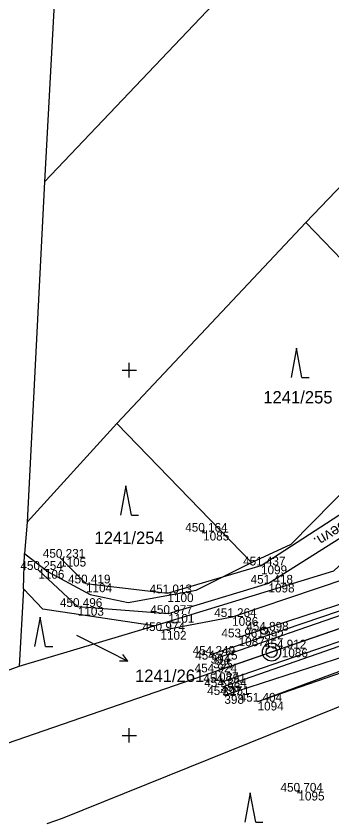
# Model space of a CAD drawing. Extents: x -776734 to -748832, y -1118122 to -976986.
# Drawn here: x -751615.5 to -751572.3, y -1114862.1 to -1114751.6 of the extents above; entities that cross this region are included whole.
import ezdxf

# ---------------------------------------------------------------- set-up
doc = ezdxf.new("R2010")
doc.units = 0
for name, color, linetype in [('KM_Hranice parcel', 7, 'Continuous'), ('KM_Parcelní čísla', 7, 'Continuous'), ('KM_Pop  PČ popisy', 7, 'Continuous'), ('KM_Značky kultur', 7, 'Continuous'), ('Level 61 Křížky', 7, 'Continuous'), ('OSA', 7, 'Continuous'), ('SŽG Vrstva 1', 7, 'Continuous'), ('SŽG Vrstva 4', 7, 'Continuous'), ('SŽG Vrstva 49', 7, 'Continuous'), ('SŽG Vrstva 51', 7, 'Continuous'), ('SŽG Vrstva 53', 7, 'Continuous'), ('SŽG Vrstva 60', 7, 'Continuous'), ('SŽG Vrstva 61', 7, 'Continuous'), ('SŽG Vrstva 7', 7, 'Continuous')]:
    doc.layers.add(name, color=color, linetype=linetype)

msp = doc.modelspace()

# ---------------------------------------------------------------- linework, layer by layer
at = {"layer": 'KM_Hranice parcel'}
for p, q in [((-751499.96, -1114656.64), (-751611.61, -1114774.25)), ((-751608.83, -1114722.39), (-751611.61, -1114774.25)), ((-751575.82, -1114779.78), (-751549.39, -1114752.11)), ((-751611.61, -1114774.25), (-751614, -1114820.83)), ((-751601.71, -1114807.3), (-751575.82, -1114779.78)), ((-751554.36, -1114802.22), (-751575.82, -1114779.78)), ((-751614, -1114820.83), (-751601.71, -1114807.3)), ((-751583.25, -1114826.36), (-751601.71, -1114807.3)), ((-751614, -1114820.83), (-751614.35, -1114825.11)), ((-751614.51, -1114829.93), (-751614.35, -1114825.11)), ((-751596.62, -1114835), (-751572.02, -1114827.5)), ((-751614.51, -1114829.93), (-751615.07, -1114840.52)), ((-751615.07, -1114840.52), (-751596.62, -1114835)), ((-751620.9, -1114842.7), (-751615.07, -1114840.52))]:
    msp.add_line(p, q, dxfattribs=at)
for points in [[(-751583.25, -1114826.36), (-751577.85, -1114823.81), (-751560.69, -1114806.38), (-751554.36, -1114802.22)], [(-751614.35, -1114825.11), (-751611.11, -1114827.63), (-751605.34, -1114830.73), (-751600.16, -1114831.83), (-751590.87, -1114830.15), (-751583.25, -1114826.36)], [(-751596.62, -1114835), (-751611.86, -1114832.73), (-751614.51, -1114829.93)], [(-751569.13, -1114845.24), (-751609.21, -1114861.38), (-751611.28, -1114862.12)]]:
    msp.add_lwpolyline(points, dxfattribs=at)
at = {"layer": 'KM_Pop  PČ popisy'}
for p, q in [((-751607.21, -1114836.31), (-751602.9, -1114838.49)), ((-751602.9, -1114838.49), (-751600.226, -1114839.852)), ((-751600.226, -1114839.852), (-751601.346, -1114839.844)), ((-751600.226, -1114839.852), (-751600.891, -1114838.952))]:
    msp.add_line(p, q, dxfattribs=at)
at = {"layer": 'KM_Značky kultur'}
for p, q in [((-751577.11, -1114797.02), (-751577.86, -1114801.02)), ((-751576.36, -1114801.02), (-751577.11, -1114797.02)), ((-751576.36, -1114801.02), (-751575.364, -1114801.02)), ((-751600.47, -1114815.84), (-751601.22, -1114819.84)), ((-751599.72, -1114819.84), (-751600.47, -1114815.84)), ((-751599.72, -1114819.84), (-751598.724, -1114819.84)), ((-751612.21, -1114833.84), (-751612.96, -1114837.84)), ((-751611.46, -1114837.84), (-751612.21, -1114833.84)), ((-751611.46, -1114837.84), (-751610.464, -1114837.84)), ((-751583.45, -1114857.87), (-751584.2, -1114861.87)), ((-751582.7, -1114861.87), (-751583.45, -1114857.87)), ((-751582.7, -1114861.87), (-751581.704, -1114861.87))]:
    msp.add_line(p, q, dxfattribs=at)
at = {"layer": 'Level 61 Křížky'}
for p, q in [((-751600, -1114800), (-751600, -1114799)), ((-751601, -1114800), (-751599, -1114800)), ((-751600, -1114801), (-751600, -1114800)), ((-751600, -1114850), (-751600, -1114849)), ((-751601, -1114850), (-751599, -1114850)), ((-751600, -1114851), (-751600, -1114850))]:
    msp.add_line(p, q, dxfattribs=at)
at = {"layer": 'OSA'}
msp.add_line((-751305.6868, -1114743.777), (-751648.6661, -1114862.1099), dxfattribs=at)
at = {"layer": 'SŽG Vrstva 1'}
msp.add_lwpolyline([(-751493.406, -1114808.538), (-751502.885, -1114811.809), (-751512.358, -1114815.079), (-751523.744, -1114819.014), (-751530.663, -1114821.401), (-751541.116, -1114825.002), (-751550.726, -1114828.317), (-751560.172, -1114831.578), (-751569.853, -1114834.918), (-751579.125, -1114838.113), (-751588.602, -1114841.381)], dxfattribs=at)
at = {"layer": 'SŽG Vrstva 4'}
for points in [[(-751531.222, -1114820.049), (-751532.411, -1114819.814), (-751547.631, -1114824.789), (-751568.7, -1114832.128), (-751588.868, -1114838.968)], [(-751531.222, -1114820.049), (-751547.578, -1114825.515), (-751568.497, -1114832.683), (-751588.528, -1114839.629)], [(-751529.854, -1114822.836), (-751546.799, -1114828.717), (-751567.35, -1114835.812), (-751587.5, -1114842.776)], [(-751529.854, -1114822.836), (-751530.62, -1114823.702), (-751546.636, -1114829.261), (-751567.254, -1114836.441), (-751587.282, -1114843.385)]]:
    msp.add_lwpolyline(points, dxfattribs=at)
at = {"layer": 'SŽG Vrstva 49'}
for p, q in [((-751589.669, -1114822.2351), (-751590.119, -1114822.0169)), ((-751589.7849, -1114821.901), (-751590.0031, -1114822.351)), ((-751534.993, -1114829.012), (-751582.438, -1114845.392)), ((-751576.621, -1114857.8241), (-751577.071, -1114857.6059)), ((-751576.7369, -1114857.49), (-751576.9551, -1114857.94))]:
    msp.add_line(p, q, dxfattribs=at)
for points in [[(-751564.092, -1114818.587), (-751543.018, -1114806.139), (-751536.934, -1114809.473), (-751533.922, -1114815.785), (-751539.386, -1114818.117), (-751585.925, -1114833.806), (-751595.742, -1114835.716)], [(-751535.601, -1114808.255), (-751531.347, -1114816.521), (-751539.042, -1114819.748), (-751551.843, -1114824.829), (-751553.747, -1114826.383), (-751585.03, -1114836.593)], [(-751586.983, -1114844.483), (-751566.691, -1114837.92), (-751546.322, -1114830.244), (-751529.778, -1114824.115), (-751528.71, -1114826.495)], [(-751535.416, -1114827.991), (-751582.438, -1114845.392)]]:
    msp.add_lwpolyline(points, dxfattribs=at)
at = {"layer": 'SŽG Vrstva 51'}
msp.add_lwpolyline([(-751609.483, -1114825.691), (-751605.933, -1114829.205), (-751594.773, -1114830.558), (-751581.97, -1114826.747), (-751566.399, -1114816.669), (-751540.967, -1114801.189), (-751532.595, -1114806.752), (-751528.368, -1114813.336), (-751525.848, -1114818.694), (-751529.358, -1114819.936), (-751530.249, -1114815.352), (-751535.601, -1114808.255), (-751541.69, -1114804.508), (-751564.092, -1114818.587), (-751580.945, -1114829.238), (-751594.664, -1114833.383), (-751607.051, -1114832.427), (-751612.458, -1114827.357)], dxfattribs=at)
at = {"layer": 'SŽG Vrstva 53'}
for points in [[(-751615.07, -1114840.52), (-751596.62, -1114835), (-751572.02, -1114827.5), (-751551.31, -1114808.23), (-751526.51, -1114811.39), (-751501.68, -1114801.88), (-751460.63, -1114785.23), (-751418.82, -1114768.72), (-751390.21, -1114757.9), (-751377.2, -1114753.63), (-751337.18, -1114740.99), (-751293.44, -1114727.24), (-751276.39, -1114722.19), (-751236.9, -1114707.02), (-751193.03, -1114664.28), (-751178.42, -1114675.26), (-751174.34, -1114678.03), (-751162.9, -1114674.22), (-751118.39, -1114659.47), (-751098.21, -1114652.66), (-751091.59, -1114651.24)], [(-751364.44, -1114782.53), (-751398.43, -1114791.82), (-751443.69, -1114804.18), (-751468.72, -1114811.03), (-751492.77, -1114816.96), (-751522.38, -1114824.27), (-751521.19, -1114833.04), (-751530.17, -1114829.56), (-751569.13, -1114845.24), (-751609.21, -1114861.38)]]:
    msp.add_lwpolyline(points, dxfattribs=at)
at = {"layer": 'SŽG Vrstva 60'}
for p, q in [((-751589.894, -1114822.126), (-751589.894, -1114822.126)), ((-751609.483, -1114825.691), (-751609.483, -1114825.691)), ((-751612.458, -1114827.357), (-751612.458, -1114827.357)), ((-751581.97, -1114826.747), (-751581.97, -1114826.747)), ((-751605.933, -1114829.205), (-751605.933, -1114829.205)), ((-751580.945, -1114829.238), (-751580.945, -1114829.238)), ((-751594.773, -1114830.558), (-751594.773, -1114830.558)), ((-751607.051, -1114832.427), (-751607.051, -1114832.427)), ((-751594.664, -1114833.383), (-751594.664, -1114833.383)), ((-751585.925, -1114833.806), (-751585.925, -1114833.806)), ((-751595.742, -1114835.716), (-751595.742, -1114835.716)), ((-751585.03, -1114836.593), (-751585.03, -1114836.593)), ((-751581.537, -1114835.673), (-751581.537, -1114835.673)), ((-751579.125, -1114838.113), (-751579.125, -1114838.113)), ((-751588.868, -1114838.968), (-751588.868, -1114838.968)), ((-751588.528, -1114839.629), (-751588.528, -1114839.629)), ((-751588.602, -1114841.381), (-751588.602, -1114841.381)), ((-751587.5, -1114842.776), (-751587.5, -1114842.776)), ((-751587.282, -1114843.385), (-751587.282, -1114843.385)), ((-751586.983, -1114844.483), (-751586.983, -1114844.483)), ((-751582.438, -1114845.392), (-751582.438, -1114845.392)), ((-751576.846, -1114857.715), (-751576.846, -1114857.715))]:
    msp.add_line(p, q, dxfattribs=at)
at = {"layer": 'SŽG Vrstva 7'}
msp.add_line((-751581.4897, -1114835.6567), (-751581.5843, -1114835.6893), dxfattribs=at)
for centre, radius in [((-751581.537, -1114835.673), 0.5), ((-751580.5287, -1114838.597), 1.2457), ((-751580.5287, -1114838.597), 0.7519)]:
    msp.add_circle(centre, radius, dxfattribs=at)

# ---------------------------------------------------------------- texts
at = {"layer": 'KM_Parcelní čísla'}
for s, p in [('1241/255', (-751581.66, -1114804.57)), ('1241/254', (-751604.77, -1114823.81)), ('1241/261', (-751599.22, -1114842.698))]:
    msp.add_text(s, height=1.7, dxfattribs=at).set_placement(p)
at = {"layer": 'SŽG Vrstva 51'}
msp.add_text('nezpevn.', height=1.5, rotation=211.328121, dxfattribs=at).set_placement((-751567.985, -1114818.875))
at = {"layer": 'SŽG Vrstva 60'}
for s, p in [('1085', (-751589.894, -1114823.326)), ('1105', (-751609.483, -1114826.891)), ('1106', (-751612.458, -1114828.557)), ('1099', (-751581.97, -1114827.947)), ('1104', (-751605.933, -1114830.405)), ('1098', (-751580.945, -1114830.438)), ('1100', (-751594.773, -1114831.758)), ('1103', (-751607.051, -1114833.627)), ('1101', (-751594.664, -1114834.583)), ('1086', (-751585.925, -1114835.006)), ('1102', (-751595.742, -1114836.916)), ('1087', (-751585.03, -1114837.793)), ('392', (-751581.537, -1114836.873)), ('1086', (-751579.125, -1114839.313)), ('394', (-751588.868, -1114840.168)), ('395', (-751588.528, -1114840.829)), ('1087', (-751588.602, -1114842.581)), ('396', (-751587.5, -1114843.976)), ('397', (-751587.282, -1114844.585)), ('398', (-751586.983, -1114845.683)), ('1094', (-751582.438, -1114846.592)), ('1095', (-751576.846, -1114858.915))]:
    msp.add_text(s, height=1.2, dxfattribs=at).set_placement(p)
at = {"layer": 'SŽG Vrstva 61'}
for s, p in [('450.164', (-751592.345, -1114822.126)), ('450.231', (-751611.8404, -1114825.691)), ('451.437', (-751584.4219, -1114826.747)), ('450.254', (-751614.909, -1114827.357)), ('450.419', (-751608.3867, -1114829.205)), ('451.418', (-751583.3987, -1114829.238)), ('451.013', (-751597.2249, -1114830.558)), ('450.496', (-751609.5029, -1114832.427)), ('450.977', (-751597.1159, -1114833.383)), ('451.264', (-751588.376, -1114833.806)), ('450.974', (-751598.193, -1114835.716)), ('453.961', (-751587.3874, -1114836.593)), ('454.898', (-751583.9907, -1114835.673)), ('454.249', (-751591.3217, -1114838.968)), ('454.912', (-751581.5732, -1114838.113)), ('454.725', (-751590.9841, -1114839.629)), ('454.924', (-751591.053, -1114841.381)), ('454.791', (-751589.8574, -1114842.776)), ('454.334', (-751589.733, -1114843.385)), ('454.151', (-751589.3404, -1114844.483)), ('451.404', (-751584.889, -1114845.392)), ('450.704', (-751579.297, -1114857.715))]:
    msp.add_text(s, height=1.2, dxfattribs=at).set_placement(p)

doc.saveas('drawing.dxf')
